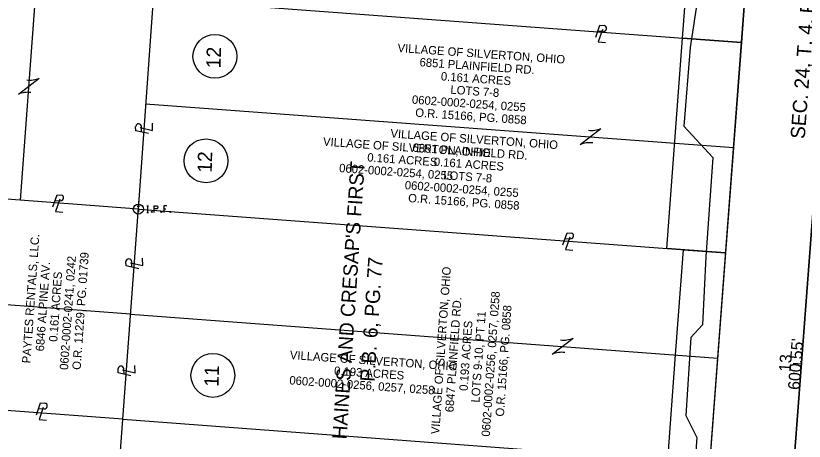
# Model space of a CAD drawing. Extents: x 204354 to 231038, y 361459 to 365260.
# Drawn here: x 220363.4 to 220550.5, y 361843.3 to 361944.2 of the extents above; entities that cross this region are included whole.
import ezdxf

# ---------------------------------------------------------------- set-up
doc = ezdxf.new("R2010")
doc.units = 0
for name, color, linetype in [('CM_Corridor_Range_Conceptual', 7, 'Continuous'), ('DT_P_Contour_Minor', 7, 'Continuous'), ('DT_P_Contour_Text', 7, 'Continuous'), ('DT_P_Triangles', 7, 'Continuous'), ('DT_X_Contour_Minor', 7, 'Continuous'), ('MD_P_CURB_BACK_BOT', 7, 'Continuous'), ('MD_P_CURB_BACK_TOP', 7, 'Continuous'), ('MD_P_Surface_Finished_Grade', 7, 'Continuous'), ('MD_P_SW_BOT', 7, 'Continuous'), ('MD_P_SW_TOP', 7, 'Continuous'), ('PV_P_Walk', 7, 'Continuous'), ('SC_Shading1', 7, 'Continuous')]:
    doc.layers.add(name, color=color, linetype=linetype)

msp = doc.modelspace()

# ---------------------------------------------------------------- linework, layer by layer
at = {"layer": 'CM_Corridor_Range_Conceptual'}
msp.add_line((220527.43, 361562.35), (220572.38, 362161.22), dxfattribs=at)
msp.add_line((220527.43, 361562.35), (220572.38, 362161.22), dxfattribs=at)
at = {"layer": 'DT_P_Contour_Text'}
for centre in [(220410.63, 361934.54), (220408.54, 361909.76), (220410.15, 361858.86)]:
    msp.add_circle(centre, 5.2, dxfattribs=at)
at = {"layer": 'DT_P_Triangles'}
msp.add_lwpolyline([(220527.79, 361965.27), (220523.44, 361936.62), (220521.94, 361918.02), (220528.8, 361910.52), (220527.14, 361886.97), (220526.37, 361870.86), (220523.6, 361867.86), (220522.4, 361849.34), (220525.02, 361844.13), (220524.29, 361834.44)], dxfattribs=at)
at = {"layer": 'MD_P_CURB_BACK_BOT'}
msp.add_line((220549.89, 361861.51), (220547.89, 361861.66), dxfattribs=at)
at = {"layer": 'MD_P_Surface_Finished_Grade'}
msp.add_line((220392.47, 361898.44), (220392.47, 361897.56), dxfattribs=at)
for points in [[(220394.5, 361899.12), (220394.85, 361899.12)], [(220394.68, 361897.52), (220394.68, 361899.12)], [(220396.24, 361897.52), (220396.24, 361899.12), (220396.77, 361899.12), (220396.83, 361899.11), (220396.9, 361899.09), (220396.94, 361899.06), (220396.97, 361899.04), (220397.01, 361898.97), (220397.05, 361898.91), (220397.07, 361898.81), (220397.07, 361898.66), (220397.06, 361898.61), (220397.04, 361898.53), (220396.99, 361898.44), (220396.95, 361898.41), (220396.92, 361898.38), (220396.86, 361898.36), (220396.77, 361898.34), (220396.24, 361898.34)], [(220399.25, 361899.12), (220398.49, 361899.12), (220398.49, 361897.52)], [(220394.5, 361897.52), (220394.85, 361897.52)], [(220395.64, 361897.74), (220395.69, 361897.74), (220395.72, 361897.71), (220395.76, 361897.66), (220395.76, 361897.6), (220395.72, 361897.55), (220395.69, 361897.52), (220395.64, 361897.52), (220395.6, 361897.55), (220395.57, 361897.6), (220395.57, 361897.66), (220395.6, 361897.71), (220395.64, 361897.74)], [(220397.89, 361897.74), (220397.94, 361897.74), (220397.97, 361897.71), (220398.01, 361897.66), (220398.01, 361897.6), (220397.97, 361897.55), (220397.94, 361897.52), (220397.89, 361897.52), (220397.85, 361897.55), (220397.82, 361897.6), (220397.82, 361897.66), (220397.85, 361897.71), (220397.89, 361897.74)], [(220398.49, 361898.34), (220399.03, 361898.34)], [(220400.03, 361897.74), (220400.09, 361897.74), (220400.12, 361897.71), (220400.16, 361897.66), (220400.16, 361897.6), (220400.12, 361897.55), (220400.09, 361897.52), (220400.03, 361897.52), (220400, 361897.55), (220399.97, 361897.6), (220399.97, 361897.66), (220400, 361897.71), (220400.03, 361897.74)]]:
    msp.add_lwpolyline(points, dxfattribs=at)
for centre, radius in [((220392.47, 361898.32), 1.2), ((220392.47, 361898.98), 0.16)]:
    msp.add_circle(centre, radius, dxfattribs=at)
at = {"layer": 'MD_P_SW_BOT'}
for p, q in [((220368.11, 361950.32), (220364.39, 361900.46)), ((220392.47, 361898.32), (220396.04, 361948.23)), ((220396.03, 361948.23), (220535.56, 361937.82)), ((220501.53, 361940.61), (220502.83, 361940.52)), ((220502.29, 361939.93), (220502.29, 361939.93)), ((220364.01, 361925.55), (220368.96, 361929.37)), ((220366.48, 361927.46), (220366.48, 361927.46)), ((220394.17, 361923.3), (220533.69, 361912.89)), ((220393.25, 361916.59), (220393.2, 361917.89)), ((220393.85, 361917.41), (220393.85, 361917.41)), ((220497.31, 361913.61), (220502.25, 361917.43)), ((220499.78, 361915.52), (220499.78, 361915.52)), ((220364.39, 361900.46), (220252.64, 361908.89)), ((220388.01, 361838.49), (220392.65, 361900.72)), ((220392.47, 361898.27), (220364.39, 361900.46)), ((220372.72, 361900.39), (220374.01, 361900.29)), ((220373.47, 361899.7), (220373.47, 361899.7)), ((220392.47, 361898.32), (220531.81, 361887.93)), ((220493.73, 361891.38), (220495.02, 361891.28)), ((220494.48, 361890.7), (220494.48, 361890.7)), ((220390.95, 361884.54), (220390.9, 361885.84)), ((220390.61, 361873.41), (220250.82, 361883.96)), ((220391.54, 361885.36), (220391.54, 361885.36)), ((220390.61, 361873.39), (220529.94, 361863)), ((220490.7, 361863.89), (220495.64, 361867.71)), ((220493.17, 361865.8), (220493.17, 361865.8)), ((220389.07, 361859.14), (220389.03, 361860.44)), ((220389.67, 361859.96), (220389.67, 361859.96)), ((220388.75, 361848.48), (220248.94, 361859.03)), ((220368.82, 361851.04), (220370.11, 361850.95)), ((220369.57, 361850.36), (220369.57, 361850.36)), ((220388.75, 361848.46), (220528.07, 361838.07))]:
    msp.add_line(p, q, dxfattribs=at)
for points in [[(220501, 361939.06), (220502, 361941.95), (220503.03, 361941.88)], [(220502.62, 361940.87), (220501.61, 361937.98), (220503.36, 361937.85)], [(220394.86, 361916.23), (220391.87, 361916.9), (220391.83, 361917.94)], [(220392.88, 361917.65), (220395.86, 361916.96), (220395.8, 361918.71)], [(220372.18, 361898.83), (220373.18, 361901.73), (220374.22, 361901.65)], [(220373.81, 361900.64), (220372.8, 361897.75), (220374.54, 361897.62)], [(220493.19, 361889.82), (220494.19, 361892.72), (220495.22, 361892.64)], [(220494.82, 361891.63), (220493.81, 361888.74), (220495.55, 361888.61)], [(220392.55, 361884.18), (220389.56, 361884.85), (220389.52, 361885.88)], [(220390.57, 361885.6), (220393.55, 361884.91), (220393.49, 361886.66)], [(220390.68, 361858.78), (220387.69, 361859.45), (220387.65, 361860.48)], [(220388.7, 361860.19), (220391.68, 361859.51), (220391.62, 361861.26)], [(220368.28, 361849.49), (220369.28, 361852.39), (220370.32, 361852.31)], [(220369.91, 361851.3), (220368.9, 361848.41), (220370.64, 361848.28)]]:
    msp.add_lwpolyline(points, dxfattribs=at)
for centre, radius, start, end in [((220502.87, 361941.2), 0.69, 266.2039, 77.061), ((220366.8, 361934.25), 5.34, 261.2021, 293.8446), ((220366.17, 361920.67), 5.34, 81.2021, 113.8446), ((220392.52, 361917.86), 0.69, 2.5465, 173.4036), ((220500.09, 361922.31), 5.34, 261.2021, 293.8446), ((220499.47, 361908.72), 5.34, 81.2021, 113.8446), ((220374.06, 361900.98), 0.69, 266.1539, 77.011), ((220495.07, 361891.97), 0.69, 266.2045, 77.0616), ((220390.21, 361885.81), 0.69, 2.5465, 173.4036), ((220493.48, 361872.59), 5.34, 261.2021, 293.8446), ((220492.85, 361859.01), 5.34, 81.2021, 113.8446), ((220388.34, 361860.4), 0.69, 2.5465, 173.4036), ((220370.16, 361851.63), 0.69, 266.1539, 77.011)]:
    msp.add_arc(centre, radius, start, end, dxfattribs=at)
at = {"layer": 'MD_P_SW_TOP'}
msp.add_line((220519.7, 361460.36), (220580.15, 362265.73), dxfattribs=at)
at = {"layer": 'PV_P_Walk'}
msp.add_line((220509.36, 361588.77), (220549.52, 362123.86), dxfattribs=at)
at = {"layer": 'SC_Shading1'}
for points in [[(220535.56, 361937.82), (220521.6, 361938.87), (220523.47, 361963.8), (220537.43, 361962.76)], [(220531.81, 361887.93), (220517.85, 361888.97), (220521.6, 361938.87), (220535.56, 361937.82)], [(220527.32, 361828.1), (220505.38, 361829.73), (220506.13, 361839.71), (220518.1, 361838.81), (220519.97, 361863.74), (220521.84, 361888.67), (220531.81, 361887.93)]]:
    msp.add_lwpolyline(points, close=True, dxfattribs=at)

# ---------------------------------------------------------------- texts
at = {"layer": 'DT_P_Contour_Minor'}
for s, height, rotation, p in [('SEC. 24, T. 4, F.R. 2', 3.4, 85.7455, (220550.6, 361914.87)), ('VILLAGE OF SILVERTON, OHIO', 2, 356, (220453.93, 361935.58)), ('6851 PLAINFIELD RD.', 2, 356, (220459.15, 361932.21)), ('0.161 ACRES', 2, 356, (220464.22, 361928.85)), ('LOTS 7-8', 2, 356, (220466.47, 361925.69)), ('0602-0002-0254, 0255', 2, 356, (220457.34, 361923.32)), ('O.R. 15166, PG. 0858', 2, 356, (220458.13, 361920.25)), ('VILLAGE OF SILVERTON, OHIO', 2, 356, (220452.24, 361915.31)), ('6851 PLAINFIELD RD.', 2, 356, (220457.46, 361911.94)), ('0.161 ACRES', 2, 356, (220462.53, 361908.58)), ("HAINES AND CRESAP'S FIRST", 3.4, 86.2229, (220441.87, 361843.63)), ('LOTS 7-8', 2, 356, (220464.78, 361905.41)), ('0602-0002-0254, 0255', 2, 356, (220455.65, 361903.04)), ('O.R. 15166, PG. 0858', 2, 356, (220456.44, 361899.98)), ('PAYTES RENTALS, LLC.', 2, 86, (220366.85, 361861.68)), ('O.R. 11229, PG. 01739', 2, 86, (220378.77, 361860.14)), ('0602-0002-0241, 0242', 2, 86, (220375.77, 361860.13)), ('6, PG. 77', 3.4, 86.2229, (220449.17, 361867.64)), ('6846 ALPINE AV.', 2, 86, (220370.06, 361864.54)), ('VILLAGE OF SILVERTON, OHIO', 2, 86, (220463.87, 361844.86)), ('0.161 ACRES', 2, 86, (220373.23, 361866.8)), ('0602-0002-0256, 0257, 0258', 2, 86, (220475.86, 361844.32)), ('6847 PLAINFIELD RD.', 2, 86, (220467.24, 361850.08)), ('O.R. 15166, PG. 0858', 2, 86, (220479.2, 361849.06)), ('LOTS 9-10, PT 11', 2, 86, (220473.41, 361852.38)), ('0.193 ACRES', 2, 86, (220470.6, 361855.15)), ('P.B.', 3.4, 86.2229, (220448.49, 361857.29))]:
    msp.add_text(s, height=height, rotation=rotation, dxfattribs=at).set_placement(p)
at = {"layer": 'DT_P_Contour_Text'}
for s, p in [('12', (220411.96, 361931.68)), ('12', (220409.87, 361906.9)), ('11', (220411.49, 361856.15))]:
    msp.add_text(s, height=3.4, rotation=88.3143, dxfattribs=at).set_placement(p)
at = {"layer": 'DT_X_Contour_Minor'}
for s, p in [('VILLAGE OF SILVERTON, OHIO', (220436.24, 361913.37)), ('0.161 ACRES', (220446.74, 361909.63)), ('0602-0002-0254, 0255', (220440.07, 361907.09)), ('VILLAGE OF SILVERTON, OHIO', (220428.37, 361862.77)), ('0.193 ACRES', (220438.87, 361859.02)), ('0602-0002-0256, 0257, 0258', (220428.25, 361856.76))]:
    msp.add_text(s, height=2, rotation=356, dxfattribs=at).set_placement(p)
at = {"layer": 'MD_P_CURB_BACK_BOT'}
msp.add_text('13', height=2.8, rotation=85.7073, dxfattribs=at).set_placement((220547.24, 361859.62))
at = {"layer": 'MD_P_CURB_BACK_TOP'}
msp.add_text("600.55'", height=2.8, rotation=85.7073, dxfattribs=at).set_placement((220549.39, 361855.37))

doc.saveas('drawing.dxf')
